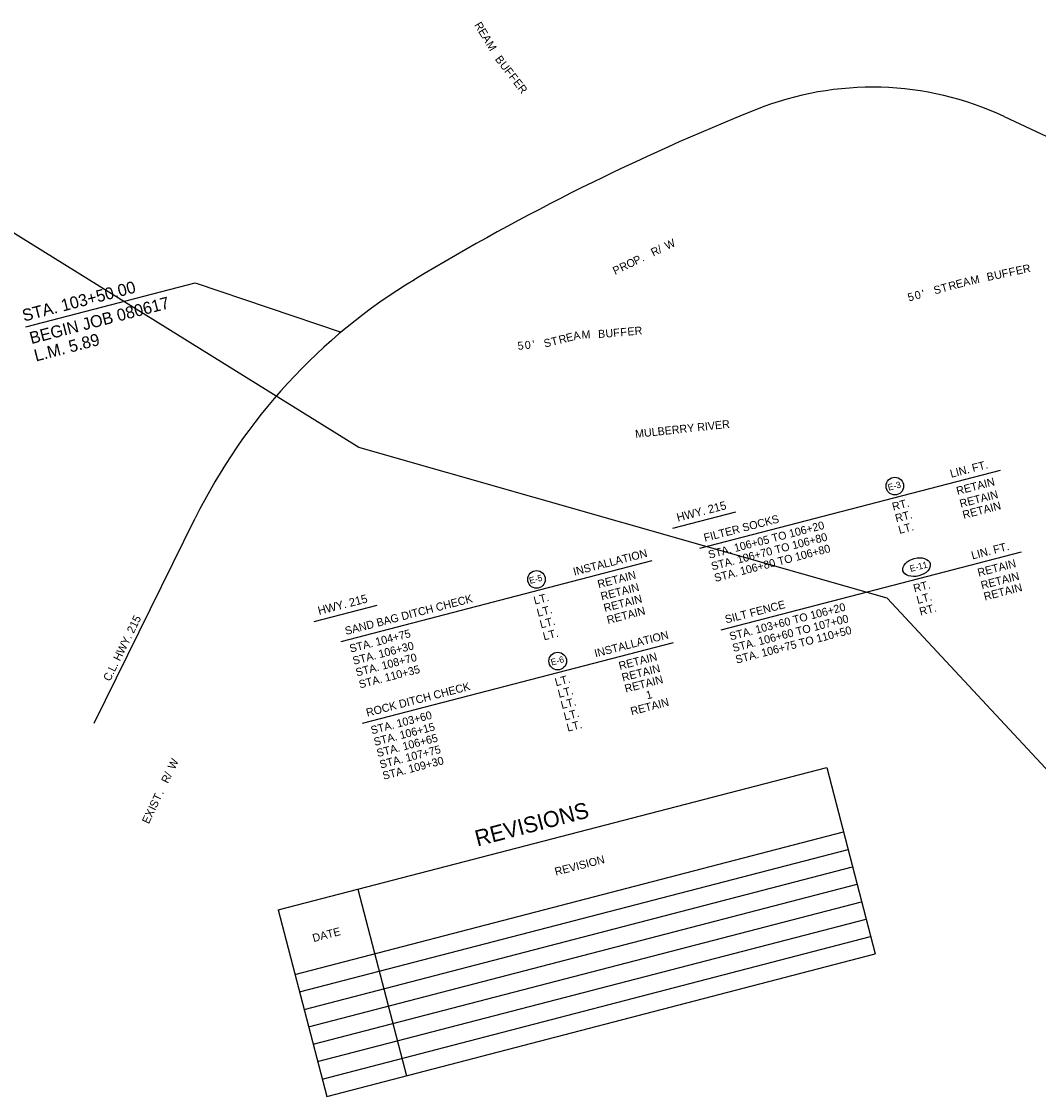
# Model space of a CAD drawing. Extents: x 830993 to 836451, y 495580 to 497751.
# Drawn here: x 834921 to 835684, y 496180 to 496986 of the extents above; entities that cross this region are included whole.
import ezdxf

# ---------------------------------------------------------------- set-up
doc = ezdxf.new("R2010")
doc.units = 0
for name, color, linetype in [('1', 7, 'Continuous'), ('44', 7, 'Continuous'), ('8', 7, 'Continuous'), ('Default', 7, 'Continuous'), ('R_Draft', 7, 'Continuous'), ('R_Horz Alg', 7, 'Continuous')]:
    doc.layers.add(name, color=color, linetype=linetype)

msp = doc.modelspace()

# ---------------------------------------------------------------- linework, layer by layer
at = {"layer": '1'}
for centre in [(835575.78, 496637.83), (835307.06, 496567.87), (835322.97, 496506.62)]:
    msp.add_circle(centre, 6.61, dxfattribs=at)
msp.add_ellipse((835592.08, 496577.04), major_axis=(10.18, 2.65), ratio=0.638788, dxfattribs=at)
at = {"layer": '44'}
for p, q in [((835429.66, 496591.23), (835654.98, 496649.77)), ((835409.37, 496606.2), (835456.64, 496618.48)), ((835160.56, 496521.31), (835393.82, 496581.92)), ((835445.58, 496529.98), (835670.9, 496588.52)), ((835140.27, 496536.28), (835187.54, 496548.56)), ((835176.47, 496460.06), (835409.74, 496520.66))]:
    msp.add_line(p, q, dxfattribs=at)
at = {"layer": '8'}
msp.add_line((835051.15, 496790.13), (835160.53, 496753.26), dxfattribs=at)
msp.add_lwpolyline([(834924.08, 496757.12), (835051.15, 496790.13)], dxfattribs=at)
at = {"layer": 'Default'}
for p, q in [((835113.37, 496320), (835524.71, 496426.87)), ((835524.71, 496426.87), (835561.05, 496287.02)), ((835125.94, 496271.61), (835537.28, 496378.48)), ((835129.34, 496258.54), (835540.68, 496365.42)), ((835132.73, 496245.48), (835544.08, 496352.35)), ((835136.13, 496232.41), (835547.47, 496339.28)), ((835136.13, 496232.41), (835547.47, 496339.28)), ((835173.19, 496335.54), (835209.53, 496195.69)), ((835139.52, 496219.34), (835550.86, 496326.22)), ((835113.37, 496320), (835149.71, 496180.14)), ((835142.92, 496206.28), (835554.26, 496313.15)), ((835146.31, 496193.21), (835557.65, 496300.09)), ((835149.71, 496180.14), (835561.05, 496287.02))]:
    msp.add_line(p, q, dxfattribs=at)
at = {"layer": 'R_Draft'}
for points in [[(835173.92, 496666.72), (834809.87, 496892.79), (833860.21, 497751.17)], [(835770.18, 496338.94), (835570.1, 496553.71), (835173.92, 496666.72)]]:
    msp.add_lwpolyline(points, dxfattribs=at)
at = {"layer": 'R_Horz Alg'}
for p, q in [((835657.74, 496914.96), (835689.37, 496900.19)), ((834975.23, 496460.02), (835051.15, 496613.79))]:
    msp.add_line(p, q, dxfattribs=at)
for centre, radius, start, end in [((835558.82, 496703.05), 233.86, 64.975, 111.7875), ((836126.36, 495283.19), 1762.95, 111.7875, 121.11111), ((835438.88, 496422.34), 432.42, 121.11111, 153.72222)]:
    msp.add_arc(centre, radius, start, end, dxfattribs=at)

# ---------------------------------------------------------------- texts
at = {"layer": '1'}
for s, rotation, p in [('E-3 ', 14.56436, (835571.14, 496634.33)), ('E-11', 14.56434, (835587.64, 496573.45)), ('E-5 ', 14.56436, (835302.26, 496564.47)), ('E-6 ', 14.56436, (835318.47, 496503.3))]:
    msp.add_text(s, height=4.8, rotation=rotation, dxfattribs=at).set_placement(p)
at = {"layer": '44'}
for s, height, rotation, p in [('LIN. FT.', 6, 14.56434, (835618.09, 496644.06)), ('RETAIN', 6, 14.56436, (835622.79, 496631.14)), ('RETAIN', 6, 14.56436, (835625.26, 496621.62)), ('HWY. 215', 6.25, 14.56436, (835413.11, 496611.08)), ('RT.', 6, 14.56434, (835574.62, 496619.32)), ('RETAIN', 6, 14.56436, (835627.44, 496613.21)), ('FILTER SOCKS', 6, 14.56434, (835433.36, 496596.07)), ('RT.', 6, 14.56434, (835576.88, 496610.61)), ('STA. 106+05 TO 106+20', 6, 14.56434, (835436.67, 496583.33)), ('LT.', 6, 14.56434, (835579.28, 496601.94)), ('STA. 106+70 TO 106+80', 6, 14.56434, (835438.93, 496574.62)), ('INSTALLATION', 6, 14.56436, (835335.43, 496570.62)), ('STA. 106+80 TO 106+80', 6, 14.56434, (835441.19, 496565.91)), ('LIN. FT.', 6, 14.56434, (835634, 496582.81)), ('RETAIN', 6, 14.56436, (835638.7, 496569.89)), ('RETAIN', 6, 14.56436, (835353.68, 496561.22)), ('RETAIN', 6, 14.56436, (835641.17, 496560.37)), ('RETAIN', 6, 14.56436, (835356.06, 496552.08)), ('RT.', 6, 14.56434, (835590.53, 496558.07)), ('RETAIN', 6, 14.56436, (835643.36, 496551.96)), ('HWY. 215', 6.25, 14.56436, (835144.01, 496541.16)), ('SAND BAG DITCH CHECK', 6, 14.56436, (835164.25, 496526.15)), ('LT.', 6, 14.56436, (835305.78, 496548.95)), ('LT.', 6, 14.56434, (835592.93, 496549.4)), ('RETAIN', 6, 14.56436, (835358.32, 496543.37)), ('SILT FENCE      ', 6, 14.56434, (835449.27, 496534.82)), ('STA. 103+60 TO 106+20', 6, 14.56434, (835452.58, 496522.08)), ('RT.', 6, 14.56434, (835595.06, 496540.65)), ('LT.', 6, 14.56436, (835308.16, 496539.8)), ('RETAIN', 6, 14.56436, (835360.66, 496534.37)), ('STA. 106+60 TO 107+00', 6, 14.56434, (835454.84, 496513.37)), ('LT.', 6, 14.56436, (835310.42, 496531.09)), ('STA. 106+75 TO 110+50', 6, 14.56434, (835457.11, 496504.66)), ('STA. 104+75', 6, 14.56436, (835167.69, 496512.92)), ('LT.', 6, 14.56436, (835312.76, 496522.1)), ('INSTALLATION', 6, 14.56436, (835351.34, 496509.37)), ('STA. 106+30', 6, 14.56436, (835170.07, 496503.77)), ('STA. 108+70', 6, 14.56436, (835172.33, 496495.06)), ('RETAIN', 6, 14.56436, (835369.6, 496499.97)), ('STA. 110+35', 6, 14.56436, (835174.67, 496486.07)), ('RETAIN', 6, 14.56436, (835371.86, 496491.26)), ('LT.', 6, 14.56436, (835321.7, 496487.7)), ('RETAIN', 6, 14.56436, (835374.03, 496482.9)), ('ROCK DITCH CHECK', 6, 14.56436, (835180.17, 496464.9)), ('LT.', 6, 14.56436, (835323.96, 496478.99)), ('1', 6, 14.56436, (835390.05, 496477.89)), ('LT.', 6, 14.56436, (835326.13, 496470.63)), ('RETAIN', 6, 14.56436, (835378.45, 496465.9)), ('STA. 103+60', 6, 14.56436, (835183.61, 496451.67)), ('LT.', 6, 14.56436, (835328.36, 496462.03)), ('STA. 106+15', 6, 14.56436, (835185.87, 496442.96)), ('LT.', 6, 14.56436, (835330.55, 496453.63)), ('STA. 106+65', 6, 14.56436, (835188.04, 496434.6)), ('STA. 107+75', 6, 14.56436, (835190.27, 496426)), ('STA. 109+30', 6, 14.56436, (835192.46, 496417.6))]:
    msp.add_text(s, height=height, rotation=rotation, dxfattribs=at).set_placement(p)
at = {"layer": '8'}
for s, height, rotation, p in [('R', 6, 301.06588, (835260.22, 496983.61)), ('E', 6, 301.06588, (835263.15, 496978.75)), ('A', 6, 301.06588, (835265.93, 496974.14)), ('M', 6, 301.06588, (835268.95, 496969.12)), ('B', 6, 307.74933, (835275.63, 496957.82)), ('U', 6, 307.74933, (835279.1, 496953.34)), ('F', 6, 307.74933, (835282.63, 496948.78)), ('F', 6, 307.74933, (835285.93, 496944.52)), ('E', 6, 307.74933, (835289.23, 496940.26)), ('R', 6, 307.74933, (835292.52, 496936)), ('W', 6, 25.6769, (835405.02, 496814.89)), ('R', 6, 25.6769, (835394.63, 496809.89)), ('/', 6, 25.6769, (835399.74, 496812.35)), ('O', 6, 25.6769, (835376.2, 496801.03)), ('P', 6, 25.6769, (835381.48, 496803.57)), ('.', 6, 25.6769, (835386.59, 496806.02)), ('P', 6, 25.6769, (835365.98, 496796.12)), ('R', 6, 25.6769, (835371.09, 496798.57)), ('U', 6, 12.15375, (835650.97, 496792.72)), ('F', 6, 12.15375, (835656.61, 496793.93)), ('F', 6, 12.19776, (835661.87, 496795.07)), ('E', 6, 12.19776, (835667.14, 496796.21)), ('R', 6, 12.19776, (835672.4, 496797.34)), ('STA. 103+50.00', 9, 14.55565, (834922.71, 496761.13)), ('R', 6, 15.25756, (835616.95, 496784.53)), ('E', 6, 15.25756, (835622.42, 496786.03)), ('A', 6, 15.25756, (835627.61, 496787.44)), ('M', 6, 12.15375, (835633.28, 496788.91)), ('B', 6, 12.15375, (835645.43, 496791.53)), ('5', 6, 15.25756, (835586.37, 496776.19)), ('0', 6, 15.25756, (835591.56, 496777.61)), ("'", 6, 15.25756, (835597.21, 496779.15)), ('S', 6, 15.25756, (835605.83, 496781.5)), ('T', 6, 15.25756, (835611.3, 496782.99)), ('BEGIN JOB 080617', 9, 14.55565, (834928.25, 496744.25)), ('L.M. 5.89', 9, 14.55565, (834931.64, 496731.18)), ('R', 6, 14.04888, (835324.52, 496744.48)), ('E', 6, 14.04888, (835330.02, 496745.86)), ('A', 6, 14.04888, (835335.24, 496747.17)), ('M', 6, 2.56072, (835340.96, 496748.36)), ('B', 6, 2.56072, (835353.37, 496748.91)), ('U', 6, 5.08824, (835359.04, 496749.15)), ('F', 6, 5.08824, (835364.78, 496749.66)), ('F', 6, 5.08824, (835370.14, 496750.14)), ('E', 6, 5.08824, (835375.51, 496750.62)), ('R', 6, 5.08824, (835380.87, 496751.09)), ('5', 6, 5.90345, (835293.22, 496739.91)), ('0', 6, 5.90345, (835298.58, 496740.47)), ("'", 6, 5.90345, (835304.4, 496741.07)), ('S', 6, 14.04888, (835313.34, 496741.68)), ('T', 6, 14.04888, (835318.84, 496743.06)), ('MULBERRY RIVER', 6, 6.1285, (835381.34, 496673.92)), ('C.L. HWY. 215', 6, 63.72222, (834987.16, 496490.97)), ('W', 6, 64.53099, (835035.66, 496424.82)), ('R', 6, 64.53099, (835030.71, 496414.42)), ('/', 6, 64.53099, (835033.14, 496419.53)), ('T', 6, 64.53099, (835024.35, 496401.06)), ('.', 6, 64.53099, (835026.87, 496406.35)), ('X', 6, 64.53099, (835018.58, 496388.95)), ('I', 6, 64.53099, (835021.06, 496394.16)), ('S', 6, 64.53099, (835021.91, 496395.95)), ('E', 6, 64.53099, (835016.26, 496384.09))]:
    msp.add_text(s, height=height, rotation=rotation, dxfattribs=at).set_placement(p)
at = {"layer": 'Default'}
for s, height, p in [('REVISIONS', 12, (835262.7, 496367.58)), ('REVISION', 6, (835321.59, 496345.69)), ('DATE', 6, (835139.92, 496295.9))]:
    msp.add_text(s, height=height, rotation=14.56436, dxfattribs=at).set_placement(p)

doc.saveas('drawing.dxf')
